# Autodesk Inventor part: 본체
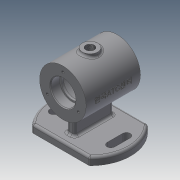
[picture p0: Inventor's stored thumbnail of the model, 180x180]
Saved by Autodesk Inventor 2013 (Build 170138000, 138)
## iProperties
Created: 2021-09
Part Number: 본체
Material: Generic
Document SubType Name: Modeling
Designer: kim
Density: 1 g/cm^3
Author: kim
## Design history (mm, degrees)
sketch "스케치1"
  geometry: C1 r 30 at (0, 0); 1 further point
  constraints: 1 centre point, 1 coincident
  dimensions: "d0" = 60 diameter of C1
extrude "돌출1" new body sketch "스케치1" stored distance "d2" = 70; taper "d3" = 0 deg
node "작업 평면1"
sketch "스케치4"
  geometry: L1 (36.742, -37.5)-(-36.742, -37.5); L2 (36.742, 37.5)-(-36.742, 37.5); A1 r 52.5 centre (0, 0) between (36.742, -37.5) and (36.742, 37.5); A2 r 52.5 centre (0, 0) between (-36.742, 37.5) and (-36.742, -37.5); 1 further point
  constraints: 4 end point, 4 point on circle, 2 centre point, 1 coincident, 1 horizontal, 1 parallel
  dimensions: "d15" = 75 distance between parallel lines of L2 L1; "d16" = 37.5 distance from line of point (0, 0) L2; "d17" = 52.5 radius of A1; "d18" = 52.5 radius of A2
extrude "돌출3" join sketch "스케치4" distance "d19" = 10; taper "d20" = 0 deg
sketch "스케치5"
  geometry: L1 (5, -25)-(-5, -25); L2 (-5, -25)-(-5, 25); L3 (-5, 25)-(5, 25); L4 (5, 25)-(5, -25); L5 (5, -25)-(-5, 25); L6 (-5, -25)-(5, 25); A1 r 52.5 centre (0, 0) between (36.742, -37.5) and (36.742, 37.5) reference
  constraints: 12 end point, 2 midpoint, 2 parallel, 1 horizontal, 1 perpendicular
  dimensions: "d21" = 50 distance of L1.end L2.end; "d23" = 10 distance of L1.start L1.end
extrude "돌출4" join sketch "스케치5" stored distance "d24" = 10; taper "d25" = 0 deg
fillet "모깎기1" dims "d26" = 3
fillet "모깎기2" dims "d27" = 3
hole "구멍1" diameter "d30" = 28; stored, may be unused: countersink angle "d34" = 90 deg, drill point angle "d36" = 0 deg; dims "d28" = 10, "d29" = 10, "d31" = 6, "d32" = 32, "d33" = 12, "d35" = 50
hole "구멍2" diameter "d39" = 28; stored, may be unused: countersink angle "d43" = 90 deg, drill point angle "d45" = 0 deg; dims "d37" = 10, "d38" = 10, "d40" = 6, "d41" = 32, "d42" = 12, "d44" = 50
sketch "스케치6"
  geometry: L1 (0, 20)-(25, 20); L2 (25, 20)-(25, -20); L3 (25, -20)-(0, -20); L4 (0, -20)-(0, 20); L5 (0, -52.5)-(0, 52.5) reference; 1 further point
  constraints: 8 end point, 2 parallel, 1 horizontal, 1 midpoint, 1 perpendicular
  dimensions: "d46" = 25 distance between parallel lines of L4 L2; "d48" = 40 distance of L1.end L2.end; "d49" = 20 distance from line of point (0, 0) L1
revolve "회전1" sketch "스케치6" stored, may be unused: angle "d50" = 90 deg
node "작업 평면2"
sketch "스케치7"
  geometry: C1 r 10 at (0, 0); 1 further point
  constraints: 1 centre point, 1 coincident
  dimensions: "d52" = 20 diameter of C1
extrude "돌출5" join sketch "스케치7" stored distance "d54" = 10; taper "d55" = 0 deg
hole "구멍3" diameter "d58" = 10.917; stored, may be unused: countersink angle "d62" = 90 deg, drill point angle "d64" = 118 deg; dims "d56" = 10, "d57" = 10, "d59" = 20, "d60" = 32, "d61" = 12, "d63" = 20
sketch "스케치8"
  geometry: L1 (-32, -10)-(-42, -10); L2 (-42, -10)-(-42, 10); L3 (-42, 10)-(-32, 10); L4 (-32, 10)-(-32, -10); L5 (-32, -10)-(-42, 10); L6 (-42, -10)-(-32, 10); A1 r 52.5 centre (0, 0) between (-36.742, 37.5) and (-36.742, -37.5) reference; A2 r 52.5 centre (0, 0) between (36.742, -37.5) and (36.742, 37.5) reference; A3 r 5 centre (-37, -10) between (-42, -10) and (-32, -10); A4 r 5 centre (-37, 10) between (-32, 10) and (-42, 10); 2 further points
  constraints: 12 end point, 5 midpoint, 4 point on circle, 2 centre point, 2 parallel, 1 horizontal, 1 horizontal alignment, 1 perpendicular
  dimensions: "d65" = 20 distance of L2.end L1.end; "d67" = 37 distance of A2.centre point (-37, 0); "d68" = 10 distance of L1.start L1.end
extrude "돌출6" cut sketch "스케치8" distance "d71" = 20; taper "d72" = 0 deg
sketch "스케치9"
  geometry: C1 r 16 at (0, 0) reference; 1 further point
  constraints: 1 vertical alignment
  dimensions: "d73" = 23 distance of point (0, 23) C1.centre
hole "구멍4" sketch "스케치9" at (0, 23) diameter "d74" = 3.242; stored, may be unused: countersink angle "d78" = 90 deg, drill point angle "d80" = 118 deg; dims "d75" = 8, "d76" = 32, "d77" = 12, "d79" = 10
node "작업 평면3"
sketch "스케치10"
  geometry: 2 further points
  constraints: 1 coincident, 1 other
feature "엠보싱1" sketch "스케치10" dims "d25" = 0, "d85" = 0.5, "d86" = 0
fillet "모깎기3" dims "d87" = 0.3
chamfer "모따기1" distance "d88" = 1; stored, may be unused: second distance "d89" = 2, angle "d90" = 45 deg
fillet "모깎기4" dims "d91" = 3
fillet "모깎기5" dims "d92" = 3
fillet "모깎기6" dims "d93" = 3
node "솔리드1"
mirror "대칭1"
pattern_circular "원형 패턴1" dims angle "d82" = 360 deg
mirror "대칭2"
other parameters: "d4" = -62, "d5" = 105, "d13" = 105, "d51" = 33
